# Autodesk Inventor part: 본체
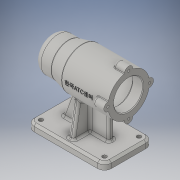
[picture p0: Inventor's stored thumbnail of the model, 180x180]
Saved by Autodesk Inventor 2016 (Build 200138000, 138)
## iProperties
Created: 2019-07
Part Number: 본체
Material: 일반
Document SubType Name: Modeling
Designer: 605-01
Density: 1 g/cm^3
Appearance: 기본값
Author: 605-01
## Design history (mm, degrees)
sketch "스케치1"
  geometry: L1 (0, 0)-(-112, 0); L2 (0, 0)-(0, 15); L3 (-10, 25)-(-25, 25); L4 (-25, 25)-(-45, 30); L5 (-45, 30)-(-112, 30); L6 (-112, 30)-(-112, 22); L7 (-111, 21)-(-97, 21); L8 (-97, 21)-(-97, 21); L9 (-94, 24)-(-46, 24); L10 (-43, 21)-(-43, 21); L11 (-43, 21)-(-31.3, 21); L12 (-31, 20.7)-(-31, 17.5); L13 (-31, 17.5)-(-13.3, 17.5); L14 (-13, 17.2)-(-13, 16); L15 (-13, 16)-(-9.3, 16); L16 (-9, 15.7)-(-9, 10.5); L17 (-9, 10.5)-(-9, 10.5); L18 (-6, 7.5)-(-6, 0); L19 (-112, 21)-(-112, 0); L20 (-111, 21)-(-112, 22); A1 r 3 centre (-9, 7.5) between (-6, 7.5) and (-9, 10.5); A2 r 0.3 centre (-9.3, 15.7) between (-9, 15.7) and (-9.3, 16); A3 r 0.3 centre (-13.3, 17.2) between (-13, 17.2) and (-13.3, 17.5); A4 r 0.3 centre (-31.3, 20.7) between (-31, 20.7) and (-31.3, 21); A5 r 3 centre (-46, 21) between (-43, 21) and (-46, 24); A6 r 3 centre (-94, 21) between (-94, 24) and (-97, 21); A7 r 10 centre (-10, 15) between (0, 15) and (-10, 25); 1 further point
  constraints: 40 end point, 14 point on circle, 14 tangent, 12 perpendicular, 7 centre point, 7 point on line, 3 equal radius, 3 horizontal, 2 vertical
  dimensions: "d0" = 50 diameter of L3 L1; "d1" = 60 diameter of L4.end L1; "d2" = 25 distance from line of L3.end L2; "d3" = 45 distance from line of L4.end L2; "d4" = 112 distance between parallel lines of L6 L2; "d5" = 42 diameter of L7 L1; "d6" = 15 distance between parallel lines of L8 L6; "d7" = 54 distance between parallel lines of L10 L8; "d8" = 48 diameter of L9 L1; "d9" = 12 distance between parallel lines of L10 L12; "d10" = 18 distance between parallel lines of L12 L14; "d11" = 35 diameter of L13 L1; "d12" = 32 diameter of L15 L1; "d13" = 3 distance between parallel lines of L16 L18; "d14" = 21 diameter of L17 L1; "d15" = 4 distance between parallel lines of L14 L16; "d16" = 3 radius of A1; "d17" = 0.3 radius of A2; "d18" = 3 radius of A5; "d19" = 1 distance of L7.start L19.start; "d20" = 1 distance of L6.end L19.start (= d19); "d21" = 10 radius of A7
revolve "회전1" sketch "스케치1" stored, may be unused: angle "d22" = 90 deg
sketch "스케치2" dims "d23" = 60
  geometry: C1 r 10.5 at (0, 0) reference; C2 r 6 at (-30, 0); C3 r 6 at (0, -30); C4 r 6 at (30, 0); C5 r 6 at (0, 30); 2 further points
  constraints: 4 centre point, 2 horizontal alignment, 1 coincident, 11 other
  dimensions: "d24" = 12 diameter of C2; "d27" = 360 deg dimension on point (0, 0) C2.centre (derived)
extrude "돌출1" join sketch "스케치2" distance "d29" = 16; taper "d30" = 0 deg
sketch "스케치3" dims "d31" = 60
  geometry: C1 r 7.5 at (30, 0) reference; 6 further points
  constraints: 2 horizontal alignment, 1 coincident, 7 other
  dimensions: "d34" = 360 deg dimension on point (30, 0) point (0, 0) (derived)
hole "구멍1" sketch "스케치3" at (0, 0), (30, -30), (60, 0), (30, 30) diameter "d36" = 3.242; stored, may be unused: countersink angle "d40" = 90 deg, drill point angle "d42" = 118 deg; dims "d37" = 8, "d38" = 4, "d39" = 2, "d41" = 11
node "작업 평면1"
sketch "스케치4"
  geometry: L1 (10, 35)-(102, 35); L2 (112, 25)-(112, -25); L3 (102, -35)-(10, -35); L4 (0, -25)-(0, 25); L5 (0, 0)-(-12.604, 0); A1 r 10 centre (10, 25) between (10, 35) and (0, 25); A2 r 10 centre (10, -25) between (0, -25) and (10, -35); A3 r 10 centre (102, -25) between (102, -35) and (112, -25); A4 r 10 centre (102, 25) between (112, 25) and (102, 35)
  constraints: 10 end point, 8 point on circle, 8 tangent, 4 centre point, 3 equal radius, 2 horizontal, 2 parallel, 1 midpoint, 1 perpendicular, 1 other
  dimensions: "d44" = 112 distance between parallel lines of L2 L4; "d45" = 70 distance between parallel lines of L3 L1; "d46" = 10 radius of A1
extrude "돌출2" join sketch "스케치4" distance "d47" = 10; taper "d48" = 0 deg
sketch "스케치5"
  geometry: A1 r 10 centre (10, 25) between (10, 35) and (0, 25) reference; A2 r 10 centre (10, -25) between (0, -25) and (10, -35) reference; A3 r 10 centre (102, -25) between (102, -35) and (112, -25) reference; A4 r 10 centre (102, 25) between (112, 25) and (102, 35) reference; 5 further points
  constraints: 4 coincident
hole "구멍2" sketch "스케치5" at (10, 25), (10, -25), (102, -25), (102, 25) diameter "d49" = 6; stored, may be unused: countersink angle "d53" = 90 deg, drill point angle "d55" = 118 deg; dims "d50" = 8, "d51" = 4, "d52" = 2, "d54" = 6
node "작업 평면2"
sketch "스케치6"
  geometry: L1 (-25, -70)-(-35, -70) reference; L2 (-28, -70)-(-19.654, -22.666); L3 (35, -70)-(25, -70) reference; L4 (28, -70)-(19.654, -22.666); L5 (-35, -80)-(-35, -70) reference; L6 (35, -80)-(35, -70) reference; L7 (-28, -70)-(-22, -70) reference; L8 (-28, -70)-(28, -70); L9 (28, -80)-(28, -70) reference; A1 r 30 centre (0, 0) between (-19.654, -22.666) and (19.654, -22.666) reference; A2 r 30 centre (0, 0) between (-19.654, -22.666) and (19.654, -22.666); 1 further point
  constraints: 6 end point, 4 point on circle, 2 point on line, 1 centre point, 1 coincident, 1 perpendicular
  dimensions: "d57" = 7 distance from line of L5 L2.start; "d58" = 7 distance from line of L6 L4.start; "d59" = 100 deg angle of L3 L4; "d60" = 100 deg angle of L1 L2
extrude "돌출3" join sketch "스케치6" stored distance "d61" = 8; taper "d62" = 0 deg
sketch "스케치7"
  geometry: L1 (56, 4)-(87, 4); L2 (87, 4)-(87, -4); L3 (87, -4)-(56, -4); L4 (56, -4)-(56, 4); L5 (0, 0)-(-6.742, 0); L6 (112, -25)-(112, 25) reference
  constraints: 10 end point, 2 horizontal, 2 parallel, 1 perpendicular, 1 other
  dimensions: "d63" = 8 distance between parallel lines of L3 L1; "d64" = 56 distance between parallel lines of L6 L4; "d65" = 25 distance between parallel lines of L6 L2
extrude "돌출4" join sketch "스케치7" stored distance "d66" = 8; taper "d67" = 0 deg
sketch "스케치8"
  geometry: L1 (-102, -70)-(-10, -70) reference; L2 (-20, -70)-(-29.796, -43.086); L3 (0, -80)-(0, -70) reference; 1 further point
  constraints: 2 end point, 1 point on line
  dimensions: "d70" = 20 distance from line of L3 L2.start; "d71" = 110 deg angle of L1 L2
feature "리브1" sketch "스케치8" dims "d72" = 1, "d73" = 8, "d74" = 0, "d75" = 0, "d76" = 1, "d77" = 1
chamfer "모따기1" distance "d78" = 3; stored, may be unused: second distance "d79" = 2, angle "d80" = 45 deg
fillet "모깎기1" dims "d81" = 3
fillet "모깎기2" dims "d82" = 3
fillet "모깎기3" dims "d83" = 3
node "작업 평면3"
sketch "스케치9"
  geometry: L1 (33.5, 29.4)-(33.5, 5.97) reference; 2 further points
  constraints: 1 horizontal alignment, 1 other
  dimensions: "d84" = 42 distance from line of L1 point (-8.5, 0)
feature "엠보싱1" sketch "스케치9" dims "d0" = 50, "d1" = 60, "d2" = 25, "d3" = 45, "d4" = 112, "d5" = 42, "d6" = 15, "d7" = 54, "d8" = 48, "d9" = 12, "d10" = 18, "d11" = 35, "d12" = 32, "d13" = 3, "d14" = 21, "d15" = 4, "d16" = 3, "d17" = 0.3, "d18" = 3, "d19" = 1, "d20" = 1 (= d19), "d21" = 10, "d85" = 0.5, "d86" = 0
fillet "모깎기4" dims "d87" = 3
fillet "모깎기5" dims "d88" = 1
node "솔리드1"
other parameters: "d56" = 56
